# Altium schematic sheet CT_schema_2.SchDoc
size 288 x 169 mm
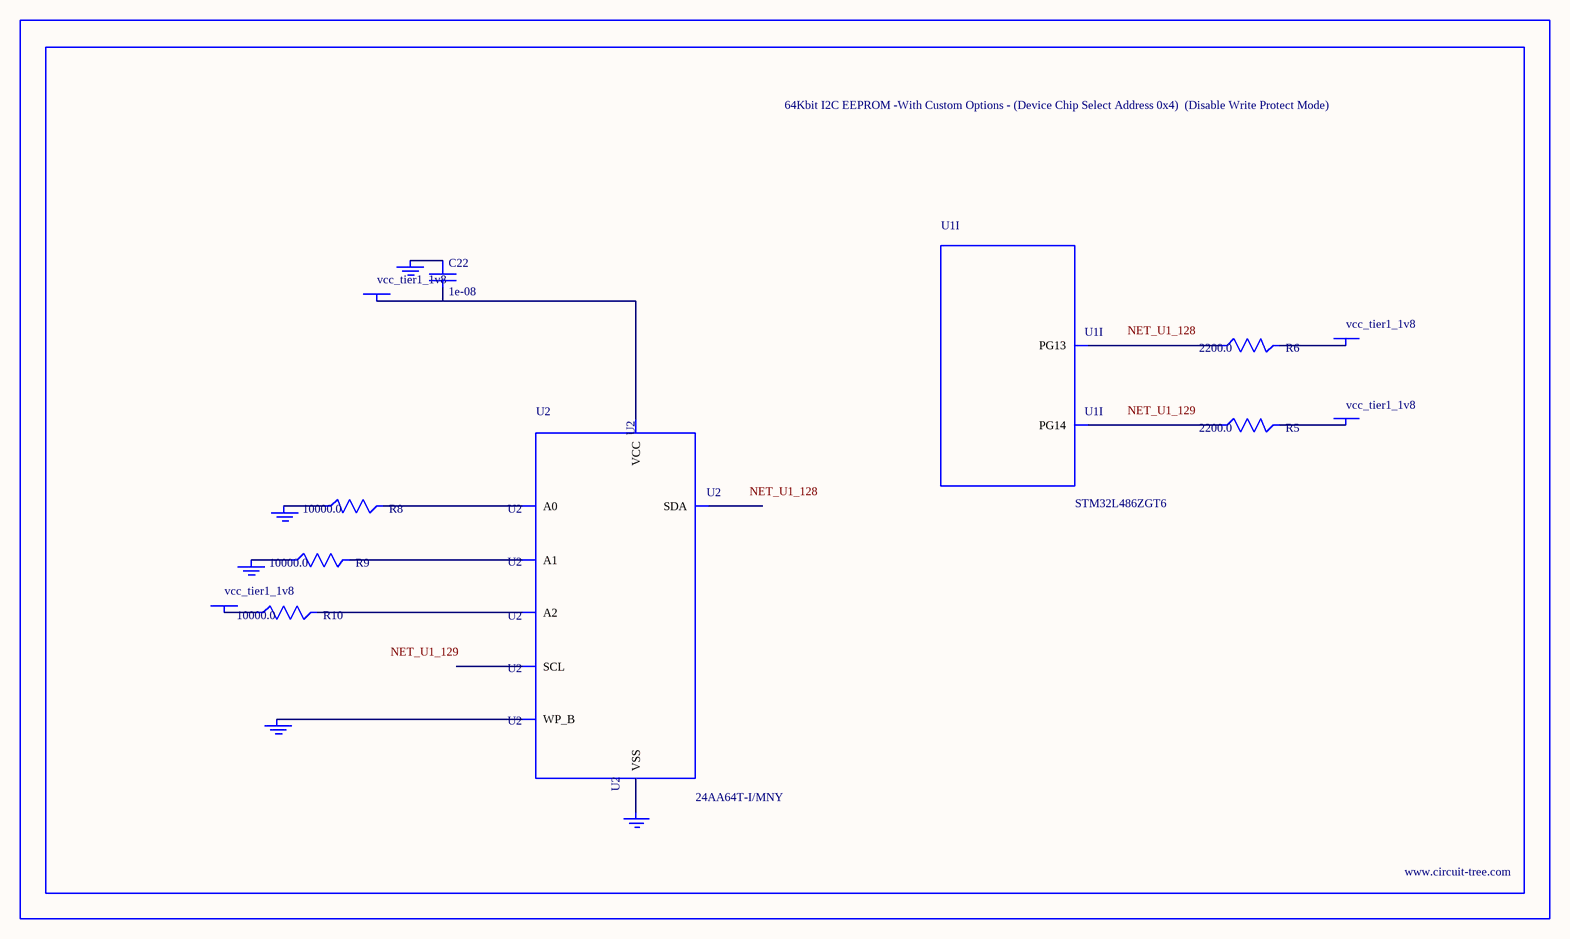
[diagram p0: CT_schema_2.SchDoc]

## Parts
BORDER1  (no value)
C22  1e-08  [C0402]
GND_INSTANCE_1_0  (no value)
GND_INSTANCE_1_1  (no value)
GND_INSTANCE_1_2  (no value)
GND_INSTANCE_1_3  (no value)
GND_INSTANCE_1_4  (no value)
POWER_INSTANCE_1_0  vcc_tier1_1v8
POWER_INSTANCE_1_1  vcc_tier1_1v8
POWER_INSTANCE_1_2  vcc_tier1_1v8
POWER_INSTANCE_1_3  vcc_tier1_1v8
R5  2200.0  [R0603]
R6  2200.0  [R0603]
R8  10000.0  [R0603]
R9  10000.0  [R0603]
R10  10000.0  [R0603]
U1  STM32L486ZGT6  [LQFP144]  (part I of 11)
U2  24AA64T-I/MNY  [TDFN-8/6MM]

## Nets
NetC22_1: C22.1 GND_INSTANCE_1_3.0(GND)
NetC22_2: C22.2 POWER_INSTANCE_1_1.0(PWR) U2.8(VCC)
NetGND_INSTANCE_1_0_0: GND_INSTANCE_1_0.0(GND) R8.1
NetGND_INSTANCE_1_1_0: GND_INSTANCE_1_1.0(GND) R9.1
NetGND_INSTANCE_1_2_0: GND_INSTANCE_1_2.0(GND) U2.7(WP_B)
NetGND_INSTANCE_1_4_0: GND_INSTANCE_1_4.0(GND) U2.4(VSS)
NetPOWER_INSTANCE_1_0_0: POWER_INSTANCE_1_0.0(PWR) R10.1
NetPOWER_INSTANCE_1_2_0: POWER_INSTANCE_1_2.0(PWR) R6.2
NetPOWER_INSTANCE_1_3_0: POWER_INSTANCE_1_3.0(PWR) R5.2
NetR5_1: R5.1 U1.129(PG14)
NetR6_1: R6.1 U1.128(PG13)
NetR8_2: R8.2 U2.1(A0)
NetR9_2: R9.2 U2.2(A1)
NetR10_2: R10.2 U2.3(A2)

Not connected (* = marked no-connect by the designer): U2 5(SDA) 6(SCL)

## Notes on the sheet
- Labels drawn without touching a wire or pin: NET_U1_128, NET_U1_129

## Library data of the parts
BORDER1 = BORDER_PAGE1
C22 = C0402C103K3RAC
GND_INSTANCE_1_0-GND_INSTANCE_1_4 = GND
POWER_INSTANCE_1_0-POWER_INSTANCE_1_3 = PWR
R5 R6 = RC0603JR-072K2L
R8-R10 = RC0603JR-0710KL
